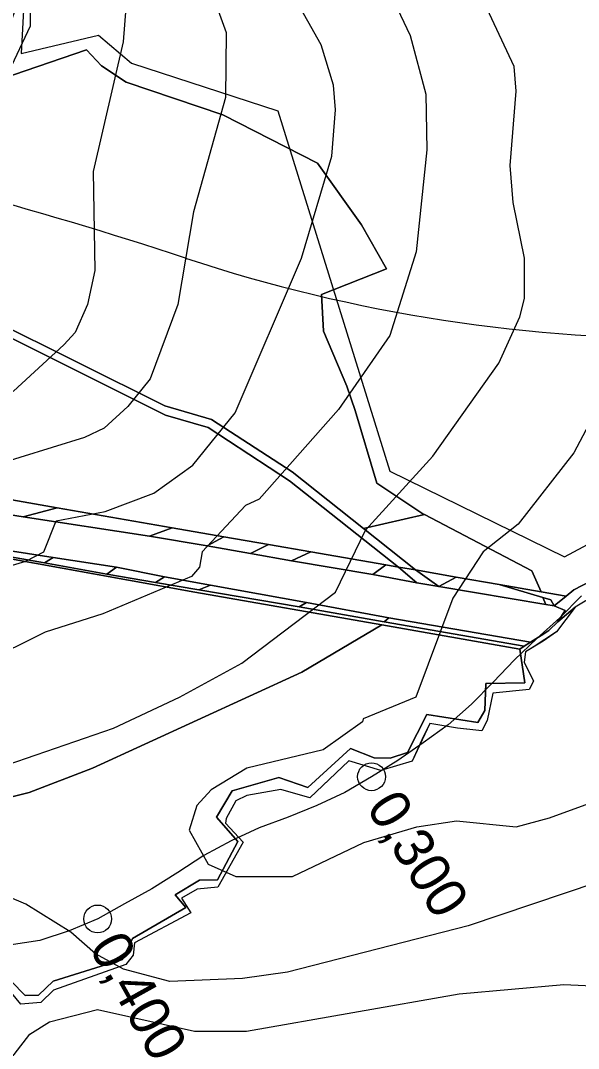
# Model space of a CAD drawing. Extents: x -510989 to -501240, y -1184665 to -1176089.
# Drawn here: x -509714 to -509533.7, y -1180893.6 to -1180561.1 of the extents above; entities that cross this region are included whole.
import ezdxf

# ---------------------------------------------------------------- set-up
doc = ezdxf.new("R2010")
doc.units = 0
for name, color, linetype in [('lesni_pozemek', 7, 'Continuous'), ('NAVRH_rozvodnice', 7, 'Continuous'), ('ostatni_plocha_x_jina_plocha', 7, 'Continuous'), ('ostatni_plocha_x_ostatni_komunikace', 7, 'Continuous'), ('ostatni_plocha_x_silnice', 7, 'Continuous'), ('popis', 7, 'Continuous'), ('STAV_systematicke_odvodneni', 7, 'Continuous'), ('trasovani_toku', 7, 'Continuous'), ('trvaly_travni_porost', 7, 'Continuous'), ('vodni_plocha_x_vodni_tok_v_koryt_prir_n_upr', 7, 'Continuous'), ('vrstevnice_01', 7, 'Continuous'), ('vrstevnice_02', 7, 'Continuous')]:
    doc.layers.add(name, color=color, linetype=linetype)

msp = doc.modelspace()

# ---------------------------------------------------------------- linework, layer by layer
at = {"layer": 'lesni_pozemek'}
for points in [[(-509687.93, -1180575.81), (-509679.92, -1180581.05), (-509648.61, -1180591.61), (-509618.01, -1180607.22), (-509603.79, -1180627.25), (-509595.76, -1180641.42), (-509616.8, -1180649.7), (-509616.1, -1180661.56), (-509608.57, -1180679.44), (-509605.88, -1180687.32), (-509598.93, -1180710.77), (-509584.03, -1180720.66), (-509583.47, -1180720.96), (-509603.14, -1180725.46), (-509626.22, -1180707.16), (-509652.32, -1180690.21), (-509667.41, -1180685.73), (-509723.75, -1180657.75), (-509738.93, -1180638.23), (-509747.74, -1180616.58), (-509741.34, -1180604.78), (-509736.21, -1180592.82), (-509735.91, -1180585.38), (-509692.78, -1180570.57)], [(-509766.63, -1180629.82), (-509745.13, -1180639.19), (-509735.71, -1180649.58), (-509725.28, -1180659.74), (-509667.15, -1180688.81), (-509653.37, -1180692.78), (-509627.16, -1180710.03), (-509591.89, -1180737.91), (-509595.92, -1180737.21), (-509620.19, -1180732.99), (-509633.91, -1180730.6), (-509648.29, -1180728.1), (-509665.08, -1180725.18), (-509702.25, -1180718.72), (-509727.96, -1180714.25), (-509747.17, -1180710.91), (-509769.56, -1180707.83), (-509791.17, -1180704.85), (-509799.83, -1180703.74), (-509814.6, -1180701.85), (-509799.96, -1180689.88), (-509787.59, -1180679.77), (-509778.32, -1180659.98)]]:
    msp.add_lwpolyline(points, close=True, dxfattribs=at)
at = {"layer": 'NAVRH_rozvodnice'}
for centre, radius, start, end in [((-510082.2, -1181912.75), 1342.63, 71.70285, 78.303), ((-509498.93, -1180148.82), 515.23, 251.7028, 270.7921)]:
    msp.add_arc(centre, radius, start, end, dxfattribs=at)
at = {"layer": 'ostatni_plocha_x_jina_plocha'}
for points in [[(-509750.19, -1180729.19), (-509742.86, -1180730.16), (-509734.35, -1180731.53), (-509727.77, -1180732.74), (-509706.34, -1180736.54), (-509686.16, -1180740.18), (-509670.43, -1180742.92), (-509656.38, -1180745.27), (-509624.02, -1180750.82), (-509596.56, -1180755.62), (-509551.24, -1180763.55), (-509552.7, -1180764.48), (-509597.31, -1180756.65), (-509657.69, -1180746.05), (-509700.64, -1180738.29), (-509763.26, -1180726.98)], [(-509559.36, -1180743.56), (-509545.8, -1180745.92), (-509537.66, -1180747.33), (-509541.54, -1180750.5), (-509542.65, -1180748.53), (-509545.23, -1180747.76)]]:
    msp.add_lwpolyline(points, close=True, dxfattribs=at)
at = {"layer": 'ostatni_plocha_x_ostatni_komunikace'}
msp.add_lwpolyline([(-509766.63, -1180629.82), (-509765.49, -1180626.89), (-509742.05, -1180636.9), (-509738.93, -1180638.23), (-509723.75, -1180657.75), (-509667.41, -1180685.73), (-509652.32, -1180690.21), (-509626.22, -1180707.16), (-509603.14, -1180725.46), (-509586.34, -1180738.87), (-509591.89, -1180737.91), (-509627.16, -1180710.03), (-509653.37, -1180692.78), (-509667.15, -1180688.81), (-509725.28, -1180659.74), (-509735.71, -1180649.58), (-509745.13, -1180639.19)], close=True, dxfattribs=at)
at = {"layer": 'ostatni_plocha_x_silnice'}
for points in [[(-509746.53, -1180716.34), (-509727.96, -1180714.25), (-509702.25, -1180718.72), (-509713.25, -1180721.66)], [(-509713.25, -1180721.66), (-509702.25, -1180718.72), (-509665.08, -1180725.18), (-509672.38, -1180727.89)], [(-509672.38, -1180727.89), (-509665.08, -1180725.18), (-509648.29, -1180728.1), (-509653.74, -1180731.02)], [(-509648.29, -1180728.1), (-509633.91, -1180730.6), (-509639.76, -1180733.52), (-509653.74, -1180731.02)], [(-509725.06, -1180731.46), (-509703.52, -1180734.87), (-509706.34, -1180736.54), (-509727.77, -1180732.74)], [(-509633.91, -1180730.6), (-509620.19, -1180732.99), (-509626.46, -1180735.96), (-509639.76, -1180733.52)], [(-509703.52, -1180734.87), (-509683.08, -1180737.98), (-509686.16, -1180740.18), (-509706.34, -1180736.54)], [(-509626.46, -1180735.96), (-509620.19, -1180732.99), (-509595.92, -1180737.21), (-509600.21, -1180740.35)], [(-509683.08, -1180737.98), (-509667.5, -1180741.1), (-509670.43, -1180742.92), (-509686.16, -1180740.18)], [(-509595.92, -1180737.21), (-509591.89, -1180737.91), (-509585.93, -1180743.01), (-509600.21, -1180740.35)], [(-509591.89, -1180737.91), (-509586.34, -1180738.87), (-509578.79, -1180744.22), (-509585.93, -1180743.01)], [(-509586.34, -1180738.87), (-509573.25, -1180741.15), (-509578.79, -1180744.22)], [(-509667.5, -1180741.1), (-509652.66, -1180743.75), (-509656.38, -1180745.27), (-509670.43, -1180742.92)], [(-509573.25, -1180741.15), (-509559.36, -1180743.56), (-509545.23, -1180747.76), (-509544.25, -1180750.04), (-509578.79, -1180744.22)], [(-509652.66, -1180743.75), (-509621.59, -1180749.38), (-509624.02, -1180750.82), (-509656.38, -1180745.27)], [(-509545.23, -1180747.76), (-509542.65, -1180748.53), (-509541.54, -1180750.5), (-509544.25, -1180750.04)], [(-509621.59, -1180749.38), (-509595.04, -1180754.33), (-509596.56, -1180755.62), (-509624.02, -1180750.82)], [(-509595.04, -1180754.33), (-509549.18, -1180762.24), (-509551.24, -1180763.55), (-509596.56, -1180755.62)]]:
    msp.add_lwpolyline(points, close=True, dxfattribs=at)
msp.add_lwpolyline([(-509746.53, -1180716.34), (-509713.25, -1180721.66), (-509672.38, -1180727.89), (-509653.74, -1180731.02), (-509639.76, -1180733.52), (-509626.46, -1180735.96), (-509600.21, -1180740.35), (-509585.93, -1180743.01), (-509578.79, -1180744.22), (-509544.25, -1180750.04), (-509541.54, -1180750.5), (-509538.03, -1180751.95), (-509538.63, -1180752.9), (-509540.39, -1180755.69), (-509543.23, -1180758.46), (-509544.95, -1180759.55), (-509547.47, -1180761.15), (-509549.18, -1180762.24), (-509595.04, -1180754.33), (-509621.59, -1180749.38), (-509652.66, -1180743.75), (-509667.5, -1180741.1), (-509683.08, -1180737.98), (-509703.52, -1180734.87), (-509725.06, -1180731.46)], dxfattribs=at)
at = {"layer": 'popis'}
msp.add_lwpolyline([(-509527.53, -1180746.61), (-509534.75, -1180750.86), (-509537.79, -1180754.88), (-509540.82, -1180758.9), (-509547.99, -1180763.6), (-509550.83, -1180765.37), (-509551.22, -1180768.7), (-509548.28, -1180774.8), (-509549.65, -1180777.54), (-509561.42, -1180778.72), (-509563.18, -1180787.54), (-509564.95, -1180790.88), (-509568.87, -1180790.49), (-509572.79, -1180790.09), (-509581.8, -1180788.53), (-509587.49, -1180800.69), (-509597.58, -1180803.75), (-509607.98, -1180800.61), (-509614.25, -1180806.59), (-509620.52, -1180812.58), (-509629.94, -1180809.83), (-509640.91, -1180811.79), (-509644.44, -1180813.56), (-509647.58, -1180819.26), (-509647.78, -1180820.82), (-509642.09, -1180826.91), (-509650.3, -1180841.52), (-509656.96, -1180842.11), (-509662.06, -1180845.05), (-509658.97, -1180849.8), (-509677.2, -1180859.43), (-509677.63, -1180863.51), (-509679.99, -1180866.46), (-509703.42, -1180874.79), (-509707.54, -1180878.81), (-509713.91, -1180879.3), (-509718.51, -1180873.81)], dxfattribs=at)
at = {"layer": 'STAV_systematicke_odvodneni'}
for p, q in [((-509710.35, -1180502.77), (-509713.82, -1180571.74)), ((-509713.82, -1180571.74), (-509688.82, -1180565.89)), ((-509688.82, -1180565.89), (-509678.18, -1180574.93)), ((-509678.18, -1180574.93), (-509630.83, -1180590.37)), ((-509630.83, -1180590.37), (-509594.66, -1180706.92)), ((-509538.27, -1180734.6), (-509429.21, -1180676.05)), ((-509594.66, -1180706.92), (-509538.27, -1180734.6))]:
    msp.add_line(p, q, dxfattribs=at)
at = {"layer": 'trasovani_toku'}
for p, q in [((-509532.68, -1180747.23), (-509539.75, -1180754.3)), ((-509539.75, -1180754.3), (-509547.16, -1180761.02)), ((-509547.16, -1180761.02), (-509554.43, -1180767.89)), ((-509554.43, -1180767.89), (-509561.31, -1180775.14)), ((-509561.31, -1180775.14), (-509568.29, -1180782.31)), ((-509568.29, -1180782.31), (-509575.78, -1180788.94)), ((-509575.78, -1180788.94), (-509583.87, -1180794.8)), ((-509583.87, -1180794.8), (-509592.1, -1180800.49)), ((-509592.1, -1180800.49), (-509600.6, -1180805.76)), ((-509600.6, -1180805.76), (-509609.23, -1180810.81)), ((-509609.23, -1180810.81), (-509618.28, -1180815.05)), ((-509618.28, -1180815.05), (-509627.56, -1180818.79)), ((-509627.56, -1180818.79), (-509636.95, -1180822.23)), ((-509636.95, -1180822.23), (-509646, -1180826.48)), ((-509646, -1180826.48), (-509654.8, -1180831.24)), ((-509654.8, -1180831.24), (-509663.18, -1180836.68)), ((-509663.18, -1180836.68), (-509671.65, -1180842)), ((-509671.65, -1180842), (-509680.41, -1180846.83)), ((-509680.41, -1180846.83), (-509689.12, -1180851.74)), ((-509689.12, -1180851.74), (-509698.35, -1180855.59)), ((-509698.35, -1180855.59), (-509707.86, -1180858.69)), ((-509707.86, -1180858.69), (-509717.73, -1180860.28))]:
    msp.add_line(p, q, dxfattribs=at)
for centre in [(-509600.6, -1180805.76), (-509689.12, -1180851.74)]:
    msp.add_circle(centre, 4.5, dxfattribs=at)
at = {"layer": 'trvaly_travni_porost'}
for points in [[(-509442.98, -1180697.39), (-509535.2, -1180745.32), (-509537.66, -1180747.33), (-509545.8, -1180745.92), (-509548.81, -1180739.19), (-509583.47, -1180720.96), (-509584.03, -1180720.66), (-509598.93, -1180710.77), (-509605.88, -1180687.32), (-509608.57, -1180679.44), (-509616.1, -1180661.56), (-509616.8, -1180649.7), (-509595.76, -1180641.42), (-509603.79, -1180627.25), (-509618.01, -1180607.22), (-509648.61, -1180591.61), (-509679.92, -1180581.05), (-509687.93, -1180575.81), (-509692.78, -1180570.57), (-509735.91, -1180585.38), (-509719.49, -1180567.82), (-509715.84, -1180557.88)], [(-510005.55, -1180824.51), (-509891.24, -1180805.07), (-509778.41, -1180786.28), (-509780.27, -1180775.21), (-509719.45, -1180761.75), (-509753.6, -1180764.23), (-509779.19, -1180769.29), (-509765.69, -1180726.57), (-509763.26, -1180726.98), (-509700.64, -1180738.29), (-509657.69, -1180746.05), (-509597.31, -1180756.65), (-509623.15, -1180771.93), (-509690.75, -1180803.02), (-509711.28, -1180810.81), (-509741.72, -1180818.44), (-509743.19, -1180814.91), (-509784.6, -1180821.47), (-509912.19, -1180842.95), (-509939.98, -1180849.43)], [(-509741.72, -1180818.44), (-509711.28, -1180810.81), (-509690.75, -1180803.02), (-509623.15, -1180771.93), (-509597.31, -1180756.65), (-509552.7, -1180764.48), (-509551.01, -1180775.39), (-509563.68, -1180775.56), (-509563.97, -1180784.28), (-509566.23, -1180788.23), (-509582.7, -1180785.59), (-509588.95, -1180797.87), (-509594.52, -1180799.77), (-509599.76, -1180799.6), (-509607.39, -1180796.59), (-509621.21, -1180809.21), (-509630.61, -1180806.01), (-509645.66, -1180810.31), (-509650.68, -1180818.86), (-509643.78, -1180826.66), (-509650.37, -1180839.11), (-509656.19, -1180839.25), (-509664.11, -1180843.91), (-509660.63, -1180848.04), (-509677.91, -1180858.03), (-509681.06, -1180864.85), (-509703.49, -1180871.91), (-509708.23, -1180876.41), (-509712.58, -1180876.52), (-509717.05, -1180871.87)]]:
    msp.add_lwpolyline(points, dxfattribs=at)
msp.add_lwpolyline([(-509603.14, -1180725.46), (-509583.47, -1180720.96), (-509548.81, -1180739.19), (-509545.8, -1180745.92), (-509559.36, -1180743.56), (-509573.25, -1180741.15), (-509586.34, -1180738.87)], close=True, dxfattribs=at)
at = {"layer": 'vodni_plocha_x_vodni_tok_v_koryt_prir_n_upr'}
msp.add_lwpolyline([(-509352.23, -1180649.99), (-509345.91, -1180650.45), (-509379.27, -1180668.49), (-509381.33, -1180669.6), (-509383.58, -1180670.75), (-509413.02, -1180686.05), (-509446.72, -1180703.91), (-509494.24, -1180728.79), (-509527.53, -1180746.61), (-509534.75, -1180750.86), (-509540.39, -1180755.69), (-509538.63, -1180752.9), (-509538.03, -1180751.95), (-509541.54, -1180750.5), (-509537.66, -1180747.33), (-509535.2, -1180745.32), (-509442.98, -1180697.39)], close=True, dxfattribs=at)
msp.add_lwpolyline([(-509717.05, -1180871.87), (-509712.58, -1180876.52), (-509708.23, -1180876.41), (-509703.49, -1180871.91), (-509681.06, -1180864.85), (-509677.91, -1180858.03), (-509660.63, -1180848.04), (-509664.11, -1180843.91), (-509656.19, -1180839.25), (-509650.37, -1180839.11), (-509643.78, -1180826.66), (-509650.68, -1180818.86), (-509645.66, -1180810.31), (-509630.61, -1180806.01), (-509621.21, -1180809.21), (-509607.39, -1180796.59), (-509599.76, -1180799.6), (-509594.52, -1180799.77), (-509588.95, -1180797.87), (-509582.7, -1180785.59), (-509566.23, -1180788.23), (-509563.97, -1180784.28), (-509563.68, -1180775.56), (-509551.01, -1180775.39), (-509552.7, -1180764.48), (-509551.24, -1180763.55), (-509549.18, -1180762.24), (-509547.47, -1180761.15), (-509544.95, -1180759.55), (-509543.23, -1180758.46), (-509540.39, -1180755.69), (-509534.75, -1180750.86), (-509540.82, -1180758.9), (-509545.15, -1180761.84), (-509550.83, -1180765.37), (-509551.22, -1180768.7), (-509548.28, -1180774.8), (-509549.65, -1180777.54), (-509561.42, -1180778.72), (-509563.18, -1180787.54), (-509564.95, -1180790.88), (-509572.79, -1180790.09), (-509581.8, -1180788.53), (-509583.77, -1180792.64), (-509587.49, -1180800.69), (-509597.58, -1180803.75), (-509607.98, -1180800.61), (-509620.52, -1180812.58), (-509629.94, -1180809.83), (-509640.91, -1180811.79), (-509644.44, -1180813.56), (-509647.58, -1180819.26), (-509647.78, -1180820.82), (-509642.09, -1180826.91), (-509650.3, -1180841.52), (-509656.96, -1180842.11), (-509662.06, -1180845.05), (-509658.97, -1180849.8), (-509677.2, -1180859.43), (-509677.63, -1180863.51), (-509679.99, -1180866.46), (-509703.42, -1180874.79), (-509707.54, -1180878.81), (-509713.91, -1180879.3), (-509718.51, -1180873.81)], dxfattribs=at)
at = {"layer": 'vrstevnice_01'}
for points in [[(-509602.81, -1180535), (-509588.09, -1180566), (-509583, -1180585), (-509582.69, -1180603), (-509586.19, -1180636), (-509594.69, -1180663), (-509611.31, -1180687), (-509636.91, -1180716), (-509641.31, -1180718), (-509655.31, -1180733), (-509656.19, -1180738), (-509658.81, -1180741), (-509687.41, -1180753), (-509706.09, -1180759), (-509726.31, -1180769), (-509750.09, -1180783), (-509797.91, -1180805), (-509829.19, -1180816), (-509897.31, -1180832), (-509909.59, -1180836), (-509922.59, -1180843)], [(-509655.91, -1180542), (-509647.59, -1180565), (-509647.81, -1180586), (-509658.19, -1180623), (-509663.19, -1180653), (-509672.19, -1180677), (-509679.41, -1180686), (-509687, -1180693), (-509693.41, -1180696), (-509735.31, -1180709), (-509747.81, -1180715), (-509753.5, -1180723), (-509778, -1180732), (-509811.09, -1180746), (-509864.09, -1180761), (-509880.81, -1180769), (-509933.09, -1180798)], [(-509711.09, -1180546), (-509710.91, -1180563), (-509721.41, -1180585), (-509730.41, -1180615), (-509739.91, -1180625), (-509751, -1180631), (-509757.59, -1180637), (-509770.81, -1180653), (-509778.69, -1180650), (-509782.5, -1180650), (-509840.31, -1180699), (-509848.5, -1180701), (-509851, -1180702), (-509853.31, -1180711), (-509880.5, -1180713), (-509905.81, -1180721), (-509928.91, -1180731)], [(-509523.59, -1180679), (-509535.19, -1180701), (-509553.19, -1180724), (-509564.5, -1180733), (-509574.31, -1180748), (-509586.31, -1180780), (-509603.31, -1180787), (-509603.5, -1180788), (-509616.19, -1180797), (-509640.91, -1180803), (-509652.41, -1180810), (-509657.09, -1180815), (-509659.59, -1180823), (-509653.41, -1180834), (-509644.5, -1180838), (-509626.09, -1180838), (-509603.09, -1180827), (-509585.91, -1180822), (-509573.09, -1180820), (-509553.81, -1180822), (-509543.09, -1180819), (-509529.19, -1180814)], [(-509724.19, -1180906), (-509711.09, -1180889), (-509704.69, -1180885), (-509689.19, -1180881), (-509657.81, -1180888), (-509641, -1180888), (-509572.31, -1180876), (-509538.41, -1180873), (-509515.41, -1180874), (-509494.09, -1180878), (-509470.41, -1180887), (-509458.81, -1180894)]]:
    msp.add_lwpolyline(points, dxfattribs=at)
at = {"layer": 'vrstevnice_02'}
for points in [[(-509928.31, -1180821), (-509887.5, -1180799), (-509828.81, -1180782), (-509772.5, -1180755), (-509745.81, -1180746), (-509712.31, -1180736), (-509706.5, -1180733), (-509702.5, -1180723), (-509686.69, -1180720), (-509671, -1180714), (-509658.31, -1180705), (-509644.69, -1180688), (-509623.19, -1180638), (-509613.41, -1180605), (-509612.19, -1180590), (-509612.91, -1180582), (-509616.91, -1180569), (-509633.19, -1180540)], [(-509721.59, -1180803), (-509684, -1180790), (-509662.69, -1180780), (-509642.5, -1180769), (-509612.19, -1180746), (-509602.5, -1180726), (-509580.81, -1180702), (-509559.41, -1180672), (-509552.69, -1180657), (-509551.19, -1180651), (-509551.19, -1180638), (-509554.81, -1180620), (-509555.81, -1180608), (-509553.81, -1180584), (-509554.5, -1180576), (-509568.91, -1180545)], [(-509680, -1180557), (-509680.91, -1180568), (-509690.59, -1180610), (-509690, -1180642), (-509692.41, -1180653), (-509696.41, -1180662), (-509700.09, -1180666), (-509716.31, -1180681), (-509730.09, -1180687), (-509750.59, -1180695), (-509769.91, -1180706), (-509789.41, -1180708), (-509792.5, -1180717), (-509835.91, -1180732), (-509872.19, -1180741), (-509894.81, -1180751), (-509926.09, -1180776)], [(-509507, -1180833), (-509569.31, -1180854), (-509627.81, -1180869), (-509642.31, -1180871), (-509665.81, -1180872), (-509680.81, -1180868), (-509689.81, -1180863), (-509697.81, -1180856), (-509712.31, -1180847), (-509724.09, -1180842)]]:
    msp.add_lwpolyline(points, dxfattribs=at)

# ---------------------------------------------------------------- texts
at = {"layer": 'trasovani_toku'}
for s, rotation, p in [('0,300', 301.9946, (-509602.57, -1180815.64)), ('0,400', 299.1872, (-509692.15, -1180860.8))]:
    msp.add_text(s, height=13, rotation=rotation, dxfattribs=at).set_placement(p)

doc.saveas('drawing.dxf')
